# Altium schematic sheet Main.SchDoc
size A3; SheetNumber: 1
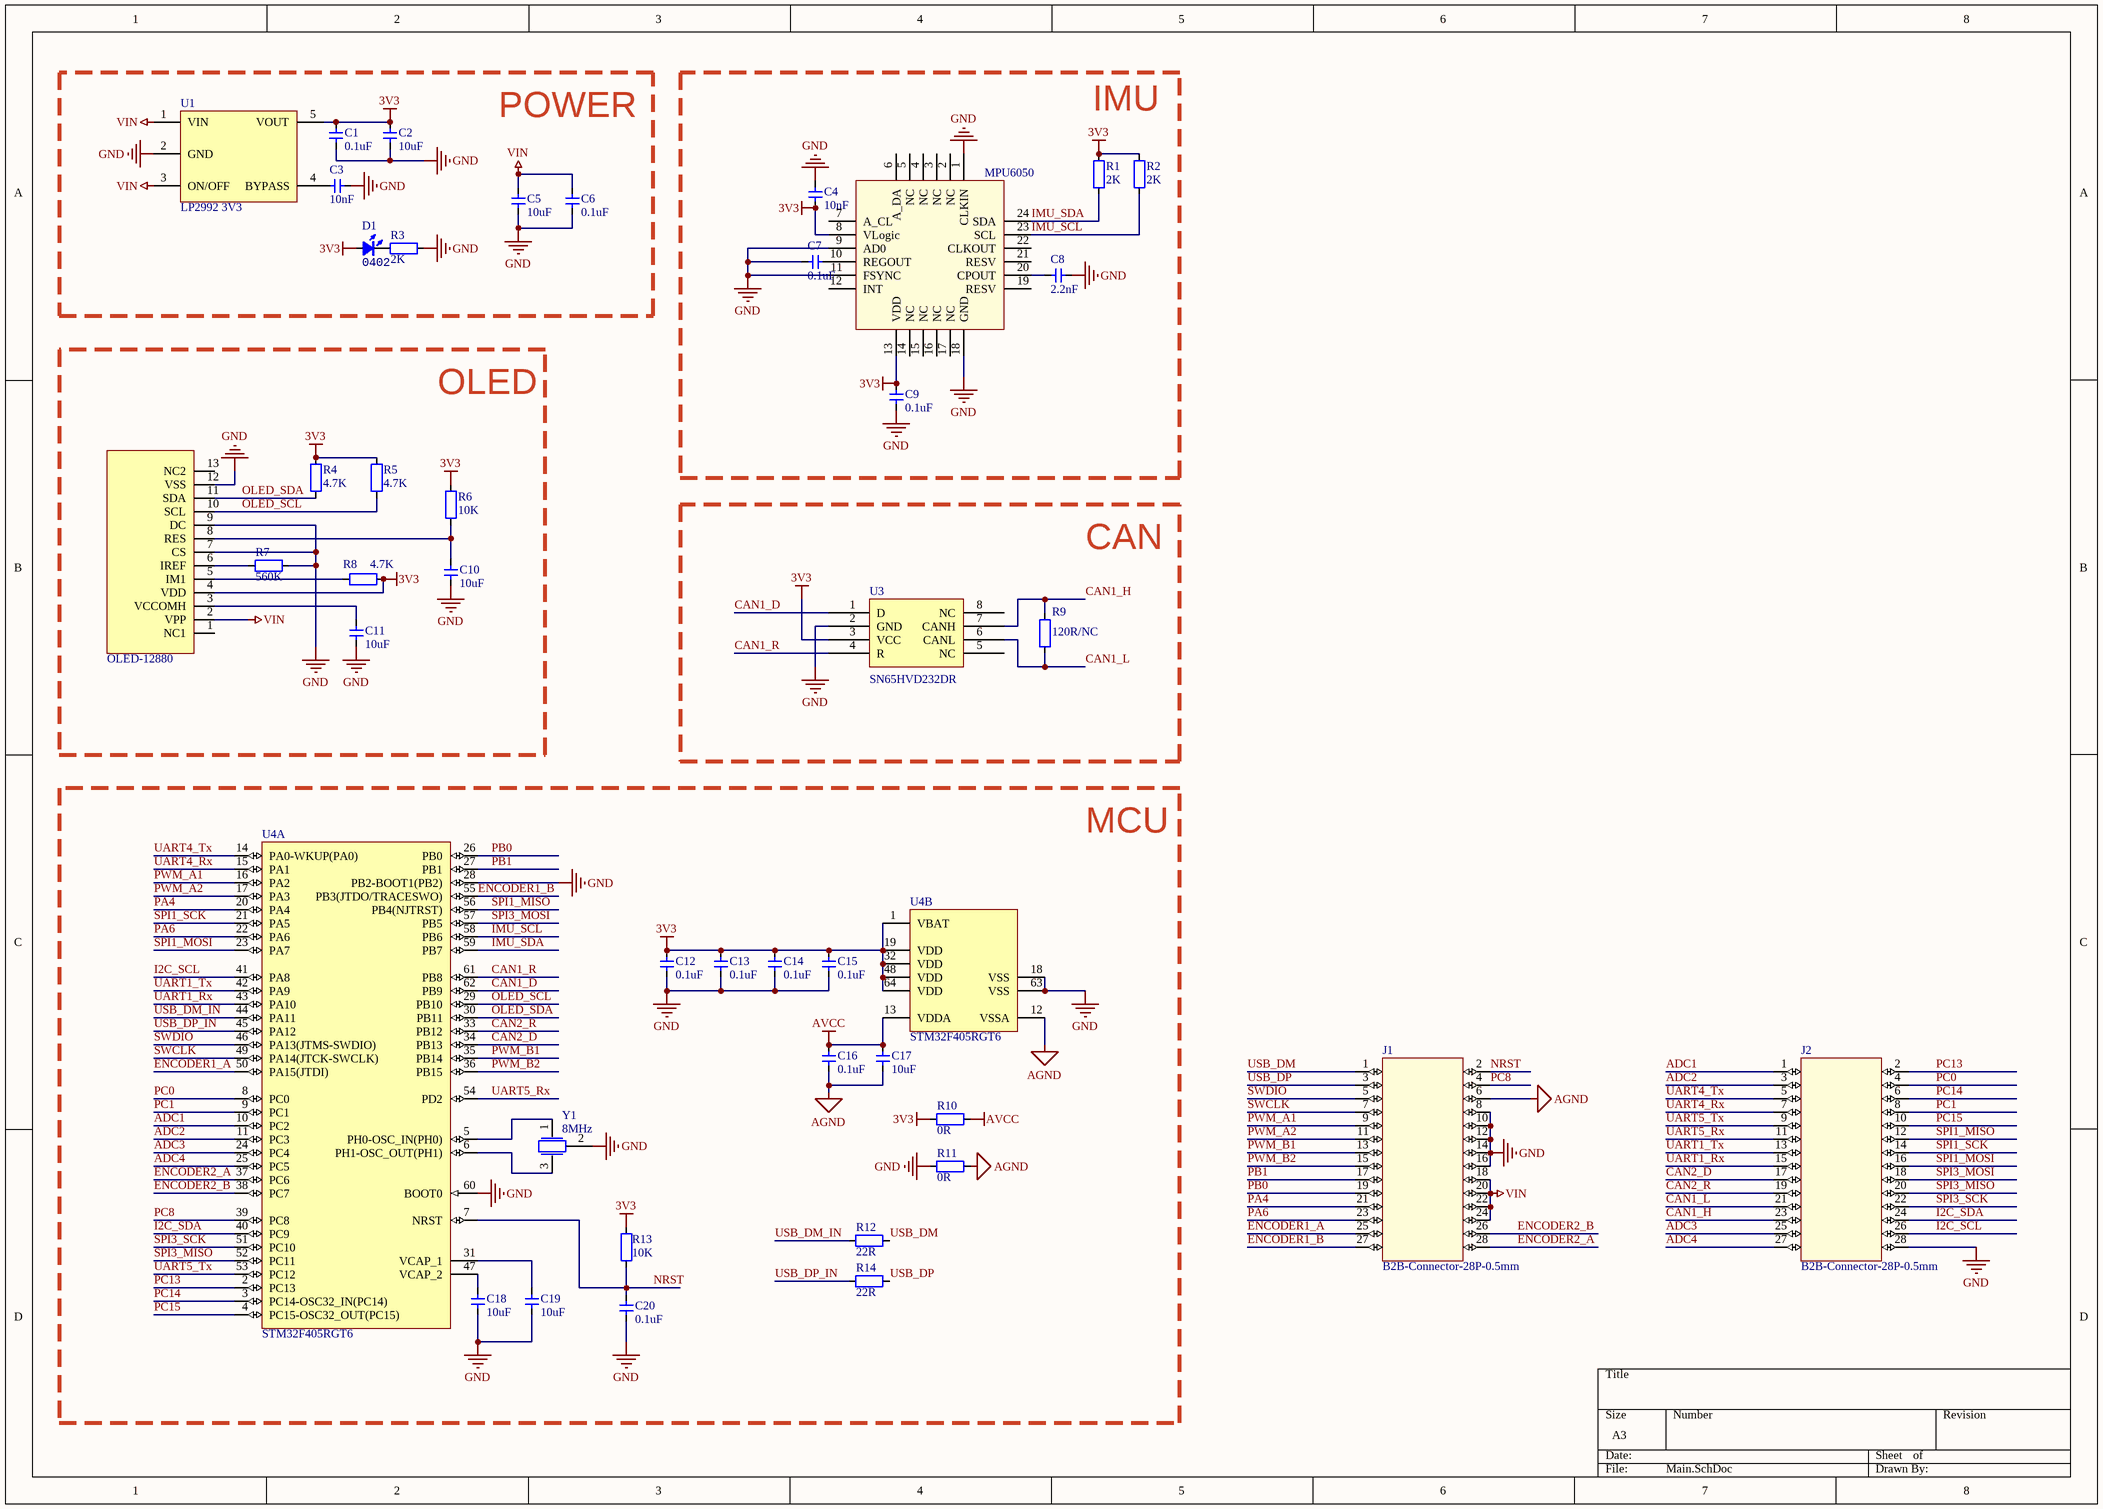
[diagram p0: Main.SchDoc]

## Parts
1  OLED-12880  [OLED-12880]
C1  0.1uF  [CAP_0402]
C2  10uF  [CAP_0402]
C3  10nF  [CAP_0402]
C4  10nF  [CAP_0402]
C5  10uF  [CAP_0402]
C6  0.1uF  [CAP_0402]
C7  0.1uF  [CAP_0402]
C8  2.2nF  [CAP_0402]
C9  0.1uF  [CAP_0402]
C10  10uF  [CAP_0402]
C11  10uF  [CAP_0402]
C12  0.1uF  [CAP_0402]
C13  0.1uF  [CAP_0402]
C14  0.1uF  [CAP_0402]
C15  0.1uF  [CAP_0402]
C16  0.1uF  [CAP_0402]
C17  10uF  [CAP_0402]
C18  10uF  [CAP_0402]
C19  10uF  [CAP_0402]
C20  0.1uF  [CAP_0402]
D1  Type: 0402  [LED_0402_RED]  (hidden comment: color?)
J1  B2B-Connector-28P-0.5mm  [B2B-0.5mm-28P-M]
J2  B2B-Connector-28P-0.5mm  [B2B-0.5mm-28P-M]
R1  2K  [RES_0402]
R2  2K  [RES_0402]
R3  2K  [RES_0402]
R4  4.7K  [RES_0402]
R5  4.7K  [RES_0402]
R6  10K  [RES_0402]
R7  560K  [RES_0402]
R8  4.7K  [RES_0402]
R9  120R/NC  [RES_0402]
R10  0R  [RES_0402]
R11  0R  [RES_0402]
R12  22R  [RES_0402]
R13  10K  [RES_0402]
R14  22R  [RES_0402]
U1  LP2992 3V3  [SOT23-5]
U2  MPU6050  [QFN-24]
U3  Manufacturer Part Number: SN65HVD232DR  [SO-8]  (hidden comment: SN65HVD232D)
U4  STM32F405RGT6  [LQFP-64_N]  (parts A,B of 2)
Y1  8MHz  [晶振-3P]

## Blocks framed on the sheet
POWER: C1-C3 C5 C6 D1 R3 U1
IMU: C4 C7-C9 R1 R2 U2
OLED: 1 C10 C11 R4-R8
CAN: R9 U3
MCU: C12-C20 R10-R14 U4 Y1

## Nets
3V3: 1.4(VDD) C1.2 C2.2 C4.1 C9.2 C12.2 C13.2 C14.2 C15.2 D1.1(A) R1.2 R2.2 R4.2 R5.2 R6.2 R8.2 R10.2 R13.2 U1.5(VOUT) U2.8(VLogic) U2.13(VDD) U3.3(VCC) U4.1(VBAT) U4.19(VDD) U4.32(VDD) U4.48(VDD) U4.64(VDD)
AGND: C16.1 C17.1 J1.6 R11.1 U4.12(VSSA)
AVCC: C16.2 C17.2 R10.1 U4.13(VDDA)
GND: 1.7(CS) 1.9(DC) 1.12(VSS) C1.1 C2.1 C3.1 C4.2 C5.1 C6.1 C7.2 C8.1 C9.1 C10.1 C11.1 C12.1 C13.1 C14.1 C15.1 C18.1 C19.1 C20.1 J1.8 J1.10 J1.12 J1.14 J1.16 J2.28 R3.1 R7.2 R11.2 U1.2(GND) U2.1(CLKIN) U2.9(AD0) U2.11(FSYNC) U2.18(GND) U3.2(GND) U4.18(VSS) U4.28(PB2-BOOT1(PB2)) U4.60(BOOT0) U4.63(VSS) Y1.2
VIN: 1.2(VPP) C5.2 C6.2 J1.18 J1.20 J1.22 J1.24 U1.1(VIN) U1.3(ON/OFF)
ADC1: J2.1 U4.10(PC2)
ADC2: J2.3 U4.11(PC3)
ADC3: J2.25 U4.24(PC4)
ADC4: J2.27 U4.25(PC5)
CAN1_D: U3.1(D) U4.62(PB9)
CAN1_H: J2.23 R9.1 U3.7(CANH)
CAN1_L: J2.21 R9.2 U3.6(CANL)
CAN1_R: U3.4(R) U4.61(PB8)
CAN2_D: J2.17 U4.34(PB13)
CAN2_R: J2.19 U4.33(PB12)
ENCODER1_A: J1.25 U4.50(PA15(JTDI))
ENCODER1_B: J1.27 U4.55(PB3(JTDO/TRACESWO))
ENCODER2_A: J1.28 U4.37(PC6)
ENCODER2_B: J1.26 U4.38(PC7)
I2C_SCL: J2.26 U4.41(PA8)
I2C_SDA: J2.24 U4.40(PC9)
IMU_SCL: R2.1 U2.23(SCL) U4.58(PB6)
IMU_SDA: R1.1 U2.24(SDA) U4.59(PB7)
NRST: C20.2 J1.2 R13.1 U4.7(NRST)
OLED_SCL: 1.10(SCL) R5.1 U4.29(PB10)
OLED_SDA: 1.11(SDA) R4.1 U4.30(PB11)
PA4: J1.21 U4.20(PA4)
PA6: J1.23 U4.22(PA6)
PB0: J1.19 U4.26(PB0)
PB1: J1.17 U4.27(PB1)
PC0: J2.4 U4.8(PC0)
PC1: J2.8 U4.9(PC1)
PC8: J1.4 U4.39(PC8)
PC13: J2.2 U4.2(PC13)
PC14: J2.6 U4.3(PC14-OSC32_IN(PC14))
PC15: J2.10 U4.4(PC15-OSC32_OUT(PC15))
PWM_A1: J1.9 U4.16(PA2)
PWM_A2: J1.11 U4.17(PA3)
PWM_B1: J1.13 U4.35(PB14)
PWM_B2: J1.15 U4.36(PB15)
SPI1_MISO: J2.12 U4.56(PB4(NJTRST))
SPI1_MOSI: J2.16 U4.23(PA7)
SPI1_SCK: J2.14 U4.21(PA5)
SPI3_MISO: J2.20 U4.52(PC11)
SPI3_MOSI: J2.18 U4.57(PB5)
SPI3_SCK: J2.22 U4.51(PC10)
SWCLK: J1.7 U4.49(PA14(JTCK-SWCLK))
SWDIO: J1.5 U4.46(PA13(JTMS-SWDIO))
UART1_Rx: J2.15 U4.43(PA10)
UART1_Tx: J2.13 U4.42(PA9)
UART4_Rx: J2.7 U4.15(PA1)
UART4_Tx: J2.5 U4.14(PA0-WKUP(PA0))
UART5_Rx: J2.11 U4.54(PD2)
UART5_Tx: J2.9 U4.53(PC12)
USB_DM: J1.1 R12.1
USB_DM_IN: R12.2 U4.44(PA11)
USB_DP: J1.3 R14.1
USB_DP_IN: R14.2 U4.45(PA12)
Net1_3: 1.3(VCCOMH) C11.2
Net1_5: 1.5(IM1) R8.1
Net1_6: 1.6(IREF) R7.1
Net1_8: 1.8(RES) C10.2 R6.1
NetC3_2: C3.2 U1.4(BYPASS)
NetC7_1: C7.1 U2.10(REGOUT)
NetC8_2: C8.2 U2.20(CPOUT)
NetC18_2: C18.2 U4.47(VCAP_2)
NetC19_2: C19.2 U4.31(VCAP_1)
NetD1_2: D1.2(K) R3.2
NetU4_5: U4.5(PH0-OSC_IN(PH0)) Y1.1
NetU4_6: U4.6(PH1-OSC_OUT(PH1)) Y1.3

Not connected (* = marked no-connect by the designer): 1 1(NC1) 13(NC2); U2 2(NC) 3(NC) 4(NC) 5(NC) 6(A_DA) 7(A_CL) 12(INT) 14(NC) 15(NC) 16(NC) 17(NC) 19(RESV) 21(RESV) 22(CLKOUT); U3 5(NC) 8(NC)

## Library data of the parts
C1-C20 = 电容-0402: Capacitor; Value: 0.1u
D1 = LED_0402: LED
R1-R11 R13 = 电阻-0402: Resistor; Value: 22R
R12 R14 = 电阻-0402: Resistor
U1 = LP2992: LDO
U2 = MPU6050: 六轴传感器
U3 = SN65HVD232D: Manufacturer: Texas Instruments; Protocol: CAN; Number of Drivers/Receivers: 1/1; Duplex: Half; Data Rate: 1Mbps; Voltage - Supply: 3 V ~ 3.6 V
U4 = STM32F405RGT6: ARM Cortex-M4 32-bit MCU+FPU, 210 DMIPS, 1024 kB Flash, 192 kB Internal RAM, 51 I/Os, 64-pin LQFP, -40 to 85 degC, Tray; Manufacturer: STMicroelectronics; D/A Converter: 2x12-bit; FLASH Size (Prog) (kB): 1024; I/Os (High Current): 51; Internal RAM Size (kB): 192; Operating Frequency(F) (Processor speed) (MHz): 168; Supply Voltage(Vcc) max (V): 3.6; Supply Voltage(Vcc) min (V): 1.8
Y1 = 晶振-3Pin: 村田贴片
